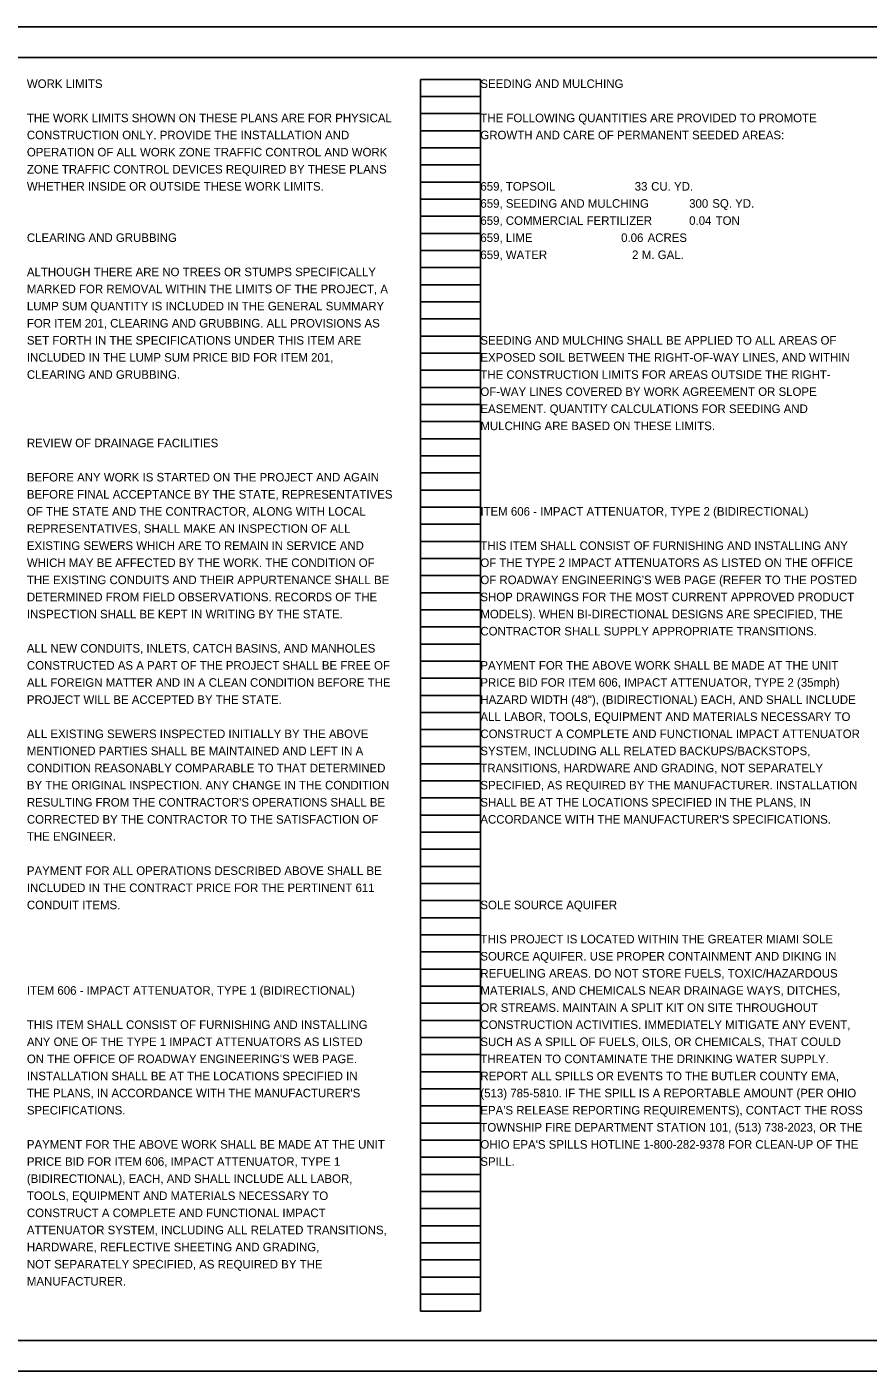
# Model space of a CAD drawing. Extents: x -10.2 to 34, y -7.1 to 22.
# Drawn here: x 9.82 to 23.58, y 0 to 22 of the extents above; entities that cross this region are included whole.
import ezdxf

# ---------------------------------------------------------------- set-up
doc = ezdxf.new("R2010")
doc.units = 0
for name, color, linetype in [('SH_Border', 7, 'Continuous'), ('SH_Cut_Line', 7, 'Continuous'), ('SH_Data', 7, 'Continuous'), ('SH_Text', 7, 'Continuous')]:
    doc.layers.add(name, color=color, linetype=linetype)

msp = doc.modelspace()

# ---------------------------------------------------------------- linework, layer by layer
at = {"layer": 'SH_Border'}
msp.add_lwpolyline([(1.5, 21.5), (33.5, 21.5), (33.5, 0.5), (1.5, 0.5)], close=True, dxfattribs=at)
at = {"layer": 'SH_Cut_Line'}
msp.add_lwpolyline([(0, 0), (34, 0), (34, 22), (0, 22)], close=True, dxfattribs=at)
at = {"layer": 'SH_Data'}
for p, q in [((16.26, 0.98), (16.26, 21.14)), ((16.26, 21.14), (17.24, 21.14)), ((17.24, 0.98), (17.24, 21.14)), ((16.26, 20.86), (17.24, 20.86)), ((16.26, 20.58), (17.24, 20.58)), ((16.26, 20.3), (17.24, 20.3)), ((16.26, 20.02), (17.24, 20.02)), ((16.26, 19.74), (17.24, 19.74)), ((16.26, 19.46), (17.24, 19.46)), ((16.26, 19.18), (17.24, 19.18)), ((16.26, 18.9), (17.24, 18.9)), ((16.26, 18.62), (17.24, 18.62)), ((16.26, 18.34), (17.24, 18.34)), ((16.26, 18.06), (17.24, 18.06)), ((16.26, 17.78), (17.24, 17.78)), ((16.26, 17.5), (17.24, 17.5)), ((16.26, 17.22), (17.24, 17.22)), ((16.26, 16.94), (17.24, 16.94)), ((16.26, 16.66), (17.24, 16.66)), ((16.26, 16.38), (17.24, 16.38)), ((16.26, 16.1), (17.24, 16.1)), ((16.26, 15.82), (17.24, 15.82)), ((16.26, 15.54), (17.24, 15.54)), ((16.26, 15.26), (17.24, 15.26)), ((16.26, 14.98), (17.24, 14.98)), ((16.26, 14.7), (17.24, 14.7)), ((16.26, 14.42), (17.24, 14.42)), ((16.26, 14.14), (17.24, 14.14)), ((16.26, 13.86), (17.24, 13.86)), ((16.26, 13.58), (17.24, 13.58)), ((16.26, 13.3), (17.24, 13.3)), ((16.26, 13.02), (17.24, 13.02)), ((16.26, 12.74), (17.24, 12.74)), ((16.26, 12.46), (17.24, 12.46)), ((16.26, 12.18), (17.24, 12.18)), ((16.26, 11.9), (17.24, 11.9)), ((16.26, 11.62), (17.24, 11.62)), ((16.26, 11.34), (17.24, 11.34)), ((16.26, 11.06), (17.24, 11.06)), ((16.26, 10.78), (17.24, 10.78)), ((16.26, 10.5), (17.24, 10.5)), ((16.26, 10.22), (17.24, 10.22)), ((16.26, 9.94), (17.24, 9.94)), ((16.26, 9.66), (17.24, 9.66)), ((16.26, 9.38), (17.24, 9.38)), ((16.26, 9.1), (17.24, 9.1)), ((16.26, 8.82), (17.24, 8.82)), ((16.26, 8.54), (17.24, 8.54)), ((16.26, 8.26), (17.24, 8.26)), ((16.26, 7.98), (17.24, 7.98)), ((16.26, 7.7), (17.24, 7.7)), ((16.26, 7.42), (17.24, 7.42)), ((16.26, 7.14), (17.24, 7.14)), ((16.26, 6.86), (17.24, 6.86)), ((16.26, 6.58), (17.24, 6.58)), ((16.26, 6.3), (17.24, 6.3)), ((16.26, 6.02), (17.24, 6.02)), ((16.26, 5.74), (17.24, 5.74)), ((16.26, 5.46), (17.24, 5.46)), ((16.26, 5.18), (17.24, 5.18)), ((16.26, 4.9), (17.24, 4.9)), ((16.26, 4.62), (17.24, 4.62)), ((16.26, 4.34), (17.24, 4.34)), ((16.26, 4.06), (17.24, 4.06)), ((16.26, 3.78), (17.24, 3.78)), ((16.26, 3.5), (17.24, 3.5)), ((16.26, 3.22), (17.24, 3.22)), ((16.26, 2.94), (17.24, 2.94)), ((16.26, 2.66), (17.24, 2.66)), ((16.26, 2.38), (17.24, 2.38)), ((16.26, 2.1), (17.24, 2.1)), ((16.26, 1.82), (17.24, 1.82)), ((16.26, 1.54), (17.24, 1.54)), ((16.26, 1.26), (17.24, 1.26)), ((16.26, 0.98), (17.24, 0.98))]:
    msp.add_line(p, q, dxfattribs=at)

# ---------------------------------------------------------------- texts
at = {"layer": 'SH_Text'}
for s, p in [('WORK LIMITS', (9.82, 21)), ('SEEDING AND MULCHING', (17.24, 21)), ('THE WORK LIMITS SHOWN ON THESE PLANS ARE FOR PHYSICAL', (9.82, 20.44)), ('THE FOLLOWING QUANTITIES ARE PROVIDED TO PROMOTE', (17.24, 20.44)), ('CONSTRUCTION ONLY. PROVIDE THE INSTALLATION AND', (9.82, 20.16)), ('GROWTH AND CARE OF PERMANENT SEEDED AREAS:', (17.24, 20.16)), ('OPERATION OF ALL WORK ZONE TRAFFIC CONTROL AND WORK', (9.82, 19.88)), ('ZONE TRAFFIC CONTROL DEVICES REQUIRED BY THESE PLANS', (9.82, 19.6)), ('WHETHER INSIDE OR OUTSIDE THESE WORK LIMITS.', (9.82, 19.32)), ('659, TOPSOIL                       ', (17.24, 19.32)), ('33', (19.765, 19.32)), (' CU. YD.', (19.982, 19.32)), ('659, SEEDING AND MULCHING          ', (17.24, 19.04)), ('300', (20.656, 19.04)), (' SQ. YD.', (20.982, 19.04)), ('659, COMMERCIAL FERTILIZER         ', (17.24, 18.76)), ('0.04', (20.656, 18.76)), (' TON', (21.037, 18.76)), ('CLEARING AND GRUBBING', (9.82, 18.48)), ('659, LIME                          ', (17.24, 18.48)), ('0.06', (19.543, 18.48)), (' ACRES', (19.924, 18.48)), ('659, WATER                         ', (17.24, 18.2)), ('2', (19.721, 18.2)), (' M. GAL.', (19.83, 18.2)), ('ALTHOUGH THERE ARE NO TREES OR STUMPS SPECIFICALLY', (9.82, 17.92)), ('MARKED FOR REMOVAL WITHIN THE LIMITS OF THE PROJECT, A', (9.82, 17.64)), ('LUMP SUM QUANTITY IS INCLUDED IN THE GENERAL SUMMARY', (9.82, 17.36)), ('FOR ITEM 201, CLEARING AND GRUBBING. ALL PROVISIONS AS', (9.82, 17.08)), ('SET FORTH IN THE SPECIFICATIONS UNDER THIS ITEM ARE', (9.82, 16.8)), ('SEEDING AND MULCHING SHALL BE APPLIED TO ALL AREAS OF', (17.24, 16.8)), ('INCLUDED IN THE LUMP SUM PRICE BID FOR ITEM 201,', (9.82, 16.52)), ('EXPOSED SOIL BETWEEN THE RIGHT-OF-WAY LINES, AND WITHIN', (17.24, 16.52)), ('CLEARING AND GRUBBING.', (9.82, 16.24)), ('THE CONSTRUCTION LIMITS FOR AREAS OUTSIDE THE RIGHT-', (17.24, 16.24)), ('OF-WAY LINES COVERED BY WORK AGREEMENT OR SLOPE', (17.24, 15.96)), ('EASEMENT. QUANTITY CALCULATIONS FOR SEEDING AND', (17.24, 15.68)), ('MULCHING ARE BASED ON THESE LIMITS.', (17.24, 15.4)), ('REVIEW OF DRAINAGE FACILITIES', (9.82, 15.12)), ('BEFORE ANY WORK IS STARTED ON THE PROJECT AND AGAIN', (9.82, 14.56)), ('BEFORE FINAL ACCEPTANCE BY THE STATE, REPRESENTATIVES', (9.82, 14.28)), ('OF THE STATE AND THE CONTRACTOR, ALONG WITH LOCAL', (9.82, 14)), ('ITEM 606 - IMPACT ATTENUATOR, TYPE 2 (BIDIRECTIONAL)', (17.24, 14)), ('REPRESENTATIVES, SHALL MAKE AN INSPECTION OF ALL', (9.82, 13.72)), ('EXISTING SEWERS WHICH ARE TO REMAIN IN SERVICE AND', (9.82, 13.44)), ('THIS ITEM SHALL CONSIST OF FURNISHING AND INSTALLING ANY', (17.24, 13.44)), ('WHICH MAY BE AFFECTED BY THE WORK. THE CONDITION OF', (9.82, 13.16)), ('OF THE TYPE 2 IMPACT ATTENUATORS AS LISTED ON THE OFFICE', (17.24, 13.16)), ('THE EXISTING CONDUITS AND THEIR APPURTENANCE SHALL BE', (9.82, 12.88)), ("OF ROADWAY ENGINEERING'S WEB PAGE (REFER TO THE POSTED", (17.24, 12.88)), ('DETERMINED FROM FIELD OBSERVATIONS. RECORDS OF THE', (9.82, 12.6)), ('SHOP DRAWINGS FOR THE MOST CURRENT APPROVED PRODUCT', (17.24, 12.6)), ('INSPECTION SHALL BE KEPT IN WRITING BY THE STATE.', (9.82, 12.32)), ('MODELS). WHEN BI-DIRECTIONAL DESIGNS ARE SPECIFIED, THE', (17.24, 12.32)), ('CONTRACTOR SHALL SUPPLY APPROPRIATE TRANSITIONS.', (17.24, 12.04)), ('ALL NEW CONDUITS, INLETS, CATCH BASINS, AND MANHOLES', (9.82, 11.76)), ('CONSTRUCTED AS A PART OF THE PROJECT SHALL BE FREE OF', (9.82, 11.48)), ('PAYMENT FOR THE ABOVE WORK SHALL BE MADE AT THE UNIT', (17.24, 11.48)), ('ALL FOREIGN MATTER AND IN A CLEAN CONDITION BEFORE THE', (9.82, 11.2)), ('PRICE BID FOR ITEM 606, IMPACT ATTENUATOR, TYPE 2 (35mph)', (17.24, 11.2)), ('PROJECT WILL BE ACCEPTED BY THE STATE.', (9.82, 10.92)), ('HAZARD WIDTH (48"), (BIDIRECTIONAL) EACH, AND SHALL INCLUDE', (17.24, 10.92)), ('ALL LABOR, TOOLS, EQUIPMENT AND MATERIALS NECESSARY TO', (17.24, 10.64)), ('ALL EXISTING SEWERS INSPECTED INITIALLY BY THE ABOVE', (9.82, 10.36)), ('CONSTRUCT A COMPLETE AND FUNCTIONAL IMPACT ATTENUATOR', (17.24, 10.36)), ('MENTIONED PARTIES SHALL BE MAINTAINED AND LEFT IN A', (9.82, 10.08)), ('SYSTEM, INCLUDING ALL RELATED BACKUPS/BACKSTOPS,', (17.24, 10.08)), ('CONDITION REASONABLY COMPARABLE TO THAT DETERMINED', (9.82, 9.8)), ('TRANSITIONS, HARDWARE AND GRADING, NOT SEPARATELY', (17.24, 9.8)), ('BY THE ORIGINAL INSPECTION. ANY CHANGE IN THE CONDITION', (9.82, 9.52)), ('SPECIFIED, AS REQUIRED BY THE MANUFACTURER. INSTALLATION ', (17.24, 9.52)), ("RESULTING FROM THE CONTRACTOR'S OPERATIONS SHALL BE", (9.82, 9.24)), ('SHALL BE AT THE LOCATIONS SPECIFIED IN THE PLANS, IN ', (17.24, 9.24)), ('CORRECTED BY THE CONTRACTOR TO THE SATISFACTION OF', (9.82, 8.96)), ("ACCORDANCE WITH THE MANUFACTURER'S SPECIFICATIONS.", (17.24, 8.96)), ('THE ENGINEER.', (9.82, 8.68)), ('PAYMENT FOR ALL OPERATIONS DESCRIBED ABOVE SHALL BE', (9.82, 8.12)), ('INCLUDED IN THE CONTRACT PRICE FOR THE PERTINENT 611', (9.82, 7.84)), ('CONDUIT ITEMS.', (9.82, 7.56)), ('SOLE SOURCE AQUIFER', (17.24, 7.56)), ('T', (17.24, 7)), ('HIS PROJECT IS LOCATED WITHIN THE GREATER MIAMI SOLE', (17.36, 7)), ('SOURCE AQUIFER. USE PROPER CONTAINMENT AND DIKING IN ', (17.24, 6.72)), ('REFUELING AREAS. DO NOT STORE FUELS, TOXIC/HAZARDOUS', (17.24, 6.44)), ('ITEM 606 - IMPACT ATTENUATOR, TYPE 1 (BIDIRECTIONAL)', (9.82, 6.16)), ('MATERIALS, AND CHEMICALS NEAR DRAINAGE WAYS, DITCHES,', (17.24, 6.16)), ('OR STREAMS. MAINTAIN A SPLIT KIT ON SITE THROUGHOUT', (17.24, 5.88)), ('THIS ITEM SHALL CONSIST OF FURNISHING AND INSTALLING', (9.82, 5.6)), ('CONSTRUCTION ACTIVITIES. IMMEDIATELY MITIGATE ANY EVENT,', (17.24, 5.6)), ('ANY ONE OF THE TYPE 1 IMPACT ATTENUATORS AS LISTED', (9.82, 5.32)), ('SUCH AS A SPILL OF FUELS, OILS, OR CHEMICALS, THAT COULD', (17.24, 5.32)), ("ON THE OFFICE OF ROADWAY ENGINEERING'S WEB PAGE.", (9.82, 5.04)), ('THREATEN TO CONTAMINATE THE DRINKING WATER SUPPLY.', (17.24, 5.04)), ('INSTALLATION SHALL BE AT THE LOCATIONS SPECIFIED IN', (9.82, 4.76)), ('REPORT ALL SPILLS OR EVENTS TO THE BUTLER COUNTY EMA,', (17.24, 4.76)), ("THE PLANS, IN ACCORDANCE WITH THE MANUFACTURER'S", (9.82, 4.48)), ('(513) 785-5810. IF THE SPILL IS A REPORTABLE AMOUNT (PER OHIO', (17.24, 4.48)), ('SPECIFICATIONS.', (9.82, 4.2)), ("EPA'S RELEASE REPORTING REQUIREMENTS), CONTACT THE ROSS", (17.24, 4.2)), ('TOWNSHIP FIRE DEPARTMENT STATION 101, (513) 738-2023, OR THE', (17.24, 3.92)), ('PAYMENT FOR THE ABOVE WORK SHALL BE MADE AT THE UNIT', (9.82, 3.64)), ("OHIO EPA'S SPILLS HOTLINE 1-800-282-9378 FOR CLEAN-UP OF THE", (17.24, 3.64)), ('PRICE BID FOR ITEM 606, IMPACT ATTENUATOR, TYPE 1', (9.82, 3.36)), ('SPILL.', (17.24, 3.36)), ('(BIDIRECTIONAL), EACH, AND SHALL INCLUDE ALL LABOR, ', (9.82, 3.08)), ('TOOLS, EQUIPMENT AND MATERIALS NECESSARY TO ', (9.82, 2.8)), ('CONSTRUCT A COMPLETE AND FUNCTIONAL IMPACT ', (9.82, 2.52)), ('ATTENUATOR SYSTEM, INCLUDING ALL RELATED TRANSITIONS, ', (9.82, 2.24)), ('HARDWARE, REFLECTIVE SHEETING AND GRADING,', (9.82, 1.96)), ('NOT SEPARATELY SPECIFIED, AS REQUIRED BY THE', (9.82, 1.68)), ('MANUFACTURER.', (9.82, 1.4))]:
    msp.add_text(s, height=0.14, dxfattribs=at).set_placement(p)

doc.saveas('drawing.dxf')
